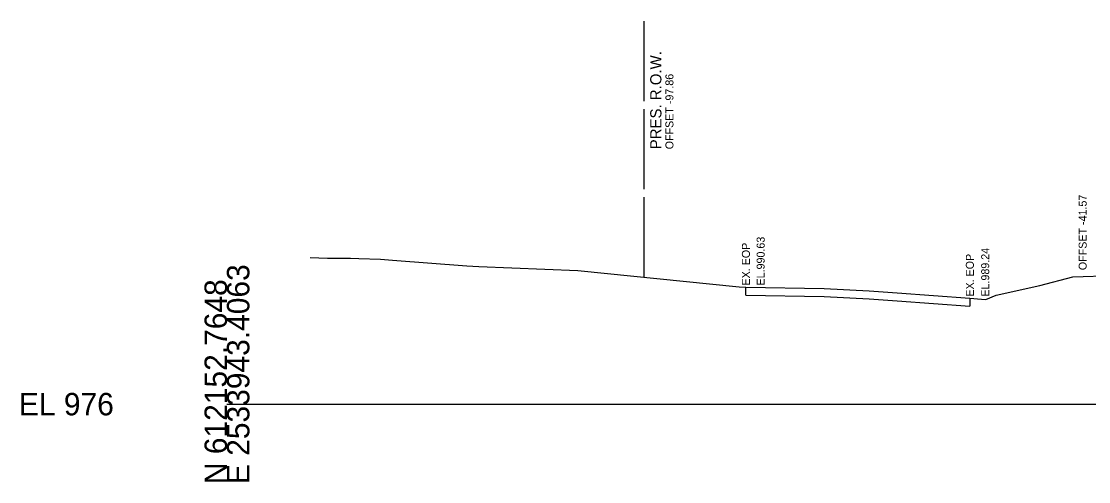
# Model space of a CAD drawing. Extents: x -120 to 2876, y -25 to 8560.
# Drawn here: x -25.7 to 107.7, y 7490.3 to 7547.9 of the extents above; entities that cross this region are included whole.
import ezdxf

# ---------------------------------------------------------------- set-up
doc = ezdxf.new("R2010")
doc.units = 0
for name, color, linetype in [('DESIGN - SHEET - Light Grid', 7, 'Continuous'), ('DESIGN - TYPICAL - Slope Tie Text', 7, 'Continuous'), ('SURVEY - GROUND - Existing Pavement Layer', 7, 'Continuous'), ('SURVEY - GROUND - Existing Pavement Text', 7, 'Continuous'), ('SURVEY - GROUND - Top of Ground', 7, 'Continuous'), ('SURVEY - PROPERTY - ROW Lines', 7, 'Continuous'), ('SURVEY - PROPERTY - ROW Lines Text', 7, 'Continuous')]:
    doc.layers.add(name, color=color, linetype=linetype)

msp = doc.modelspace()

# ---------------------------------------------------------------- linework, layer by layer
at = {"layer": 'DESIGN - SHEET - Light Grid'}
msp.add_line((0, 7500), (150, 7500), dxfattribs=at)
at = {"layer": 'SURVEY - GROUND - Existing Pavement Layer'}
for p, q in [((64.85, 7513.63), (64.85, 7514.63)), ((64.85, 7513.63), (74.63, 7513.47)), ((74.63, 7513.47), (80.23, 7513.16)), ((80.23, 7513.16), (83.75, 7512.91)), ((83.75, 7512.91), (92.83, 7512.24)), ((92.83, 7513.24), (92.83, 7512.24))]:
    msp.add_line(p, q, dxfattribs=at)
at = {"layer": 'SURVEY - GROUND - Top of Ground'}
msp.add_lwpolyline([(10.39, 7518.32), (12.55, 7518.26), (13.44, 7518.25), (15.44, 7518.24), (16.48, 7518.21), (19.19, 7518.13), (20.69, 7518.01), (29.97, 7517.31), (31.47, 7517.19), (43.86, 7516.7), (64.02, 7514.65), (64.85, 7514.63), (74.63, 7514.47), (80.23, 7514.16), (83.75, 7513.91), (92.83, 7513.24), (94.29, 7513.11), (94.84, 7513.08), (96.1, 7513.62), (101.58, 7514.82), (105.7, 7515.91), (110.83, 7516.08)], dxfattribs=at)
at = {"layer": 'SURVEY - PROPERTY - ROW Lines'}
for p, q in [((52.14, 7537.86), (52.14, 7547.86)), ((52.14, 7526.86), (52.14, 7536.86)), ((52.14, 7515.86), (52.14, 7525.86))]:
    msp.add_line(p, q, dxfattribs=at)

# ---------------------------------------------------------------- texts
at = {"layer": 'DESIGN - SHEET - Light Grid'}
for s, p in [('E 2533943.4063', (2.8, 7490)), ('N 612152.7648', (0, 7490))]:
    msp.add_text(s, height=2.8, rotation=90, dxfattribs=at).set_placement(p)
msp.add_text('EL 976', height=2.8, dxfattribs=at).set_placement((-26, 7498.6))
at = {"layer": 'DESIGN - TYPICAL - Slope Tie Text'}
msp.add_text('OFFSET -41.57', height=1, rotation=90, dxfattribs=at).set_placement((107.43, 7516.75))
at = {"layer": 'SURVEY - GROUND - Existing Pavement Text'}
for s, p in [('EL.990.63', (67.19, 7514.83)), ('EX. EOP', (65.35, 7514.83)), ('EL.989.24', (95.25, 7513.44)), ('EX. EOP', (93.33, 7513.44))]:
    msp.add_text(s, height=1, rotation=90, dxfattribs=at).set_placement(p)
at = {"layer": 'SURVEY - PROPERTY - ROW Lines Text'}
for s, height, p in [('PRES. R.O.W.', 1.4, (54.29, 7531.86)), ('OFFSET -97.86', 1, (55.79, 7531.86))]:
    msp.add_text(s, height=height, rotation=90, dxfattribs=at).set_placement(p)

doc.saveas('drawing.dxf')
